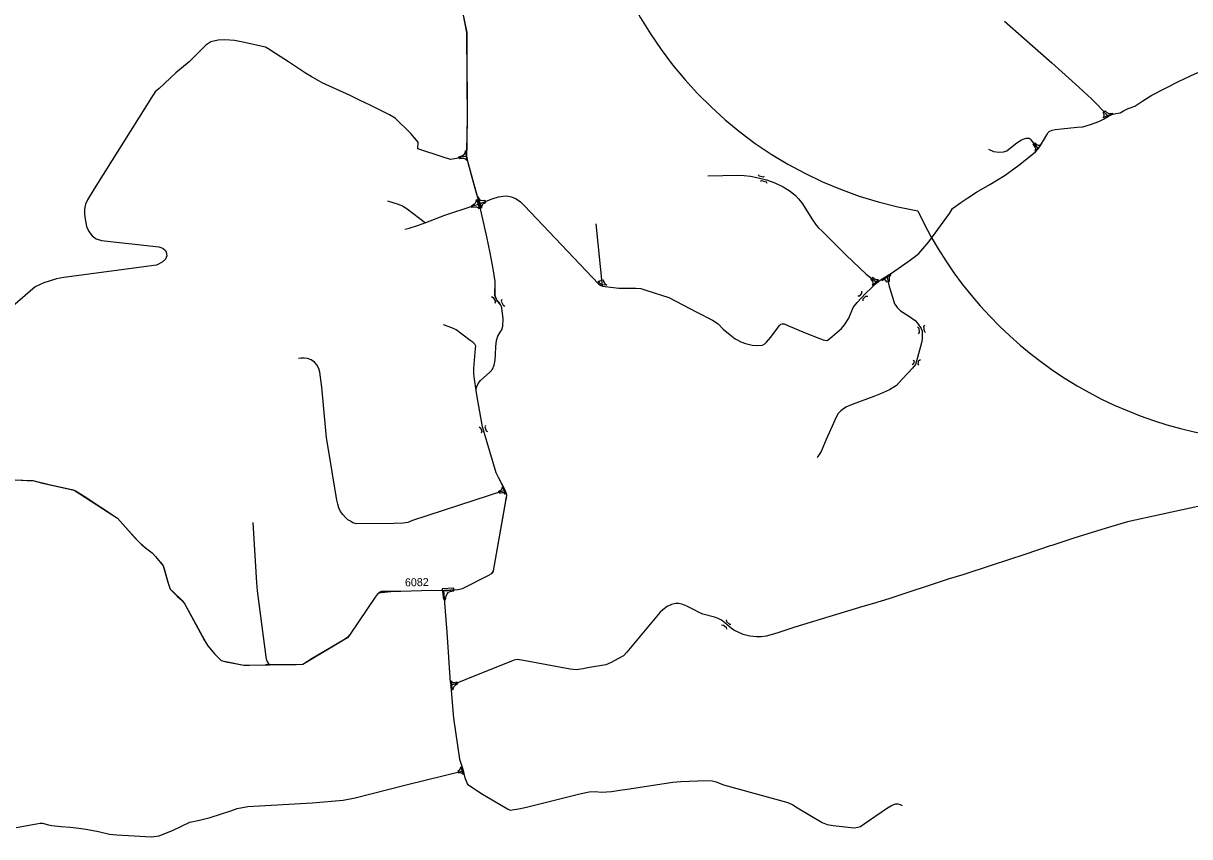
# Model space of a CAD drawing. Extents: x -444937 to -436355, y -1135022 to -1129798.
# Drawn here: x -443209 to -441751, y -1132819 to -1131803 of the extents above; entities that cross this region are included whole.
import ezdxf

# ---------------------------------------------------------------- set-up
doc = ezdxf.new("R2010")
doc.units = 0
for name, color, linetype in [('01_PARC_VNEJSI', 7, 'Continuous'), ('Vrstva 12', 7, 'Continuous'), ('Vrstva 75', 7, 'Continuous'), ('Vrstva 8', 7, 'Continuous'), ('Vrstva 84', 7, 'Continuous')]:
    doc.layers.add(name, color=color, linetype=linetype)

msp = doc.modelspace()

# ---------------------------------------------------------------- linework, layer by layer
at = {"layer": '01_PARC_VNEJSI'}
for centre, start, end in [((-442005.1, -1131544.8), 171.1162, 260.1073), ((-441638.4, -1131824.9), 205.1413, 269.9118)]:
    msp.add_arc(centre, 500, start, end, dxfattribs=at)
at = {"layer": 'Vrstva 12'}
msp.add_line((-442485.1, -1132131.6), (-442492.7, -1132053.5), dxfattribs=at)
for points in [[(-441982.7, -1131800.5), (-441958.2, -1131821.9), (-441923.5, -1131852.4), (-441889.7, -1131882.8), (-441873.4, -1131897.8), (-441866.7, -1131904.6), (-441860.5, -1131911.2), (-441854.3, -1131917.8)], [(-442654.8, -1131969.1), (-442667.5, -1131971.9), (-442674.7, -1131973.3), (-442684, -1131970.4), (-442715.8, -1131960), (-442715.4, -1131951.4), (-442724.6, -1131940.9), (-442743.9, -1131921.6), (-442750.9, -1131917.6), (-442761.2, -1131912.4), (-442774.5, -1131905.7), (-442788.4, -1131899.3), (-442800.1, -1131893.4), (-442835.1, -1131877.3), (-442849.1, -1131869.7), (-442856.2, -1131865.4), (-442877.2, -1131851.4), (-442893.4, -1131840.9), (-442901.8, -1131835.2), (-442906.1, -1131832.8), (-442934.3, -1131826.6), (-442944.6, -1131824.4), (-442956.8, -1131823.9), (-442965.2, -1131824.1), (-442974.3, -1131826.4), (-442980.8, -1131830.2), (-442989.2, -1131839.1), (-443001.4, -1131851.4), (-443018.1, -1131865.1), (-443039.1, -1131884.4), (-443043.7, -1131888.6), (-443045.2, -1131890.8), (-443047.1, -1131893.7), (-443052.5, -1131902.5), (-443120.3, -1132010), (-443128.4, -1132023.4), (-443131.1, -1132029.1), (-443132.4, -1132035.3), (-443132.4, -1132041.5), (-443131.5, -1132047.9), (-443129.5, -1132056.9), (-443126.9, -1132063.3), (-443122.7, -1132068.7), (-443117.5, -1132072.3), (-443110.9, -1132074.3), (-443039.3, -1132082.5), (-443035.6, -1132083.6), (-443033.7, -1132084.6), (-443031.1, -1132086.9), (-443030.1, -1132088.9), (-443029.5, -1132093.4), (-443030, -1132095.5), (-443030.9, -1132097.9), (-443035.2, -1132101.5), (-443042.3, -1132105.1), (-443158.1, -1132120.6), (-443167, -1132122.3), (-443176.2, -1132125.1), (-443183.1, -1132127.4), (-443193.7, -1132132.4), (-443228.1, -1132161.8)], [(-441940.7, -1131959.3), (-441949.2, -1131948.5), (-441951.7, -1131946.9), (-441955.8, -1131946.8), (-441959.9, -1131948.2), (-441962.4, -1131949.3), (-441968.7, -1131954.2), (-441979.9, -1131962.7), (-441984.5, -1131963.9), (-441989.6, -1131964.5), (-441995.8, -1131963.6), (-442002.2, -1131960.7)], [(-442353.3, -1131993.5), (-442315.8, -1131992.9), (-442308, -1131993.2), (-442299.9, -1131994.2), (-442291.9, -1131995.5), (-442280.1, -1131998.6), (-442269.5, -1132002.4), (-442259.2, -1132007.5), (-442250.3, -1132012.8), (-442243.8, -1132018.1), (-442239.9, -1132022.3), (-442235.7, -1132027.5), (-442222.5, -1132048.4), (-442217.9, -1132055.2), (-442214.9, -1132058.7), (-442210.3, -1132062.9), (-442180.5, -1132092.9), (-442155.4, -1132116.3), (-442142.2, -1132127)], [(-442753.6, -1132024.9), (-442741.7, -1132028.4), (-442735, -1132031.2), (-442728.9, -1132034.7), (-442706.2, -1132052.2)], [(-442638.9, -1132029.1), (-442646.9, -1132031.7), (-442682.3, -1132043.2), (-442706.2, -1132052.2), (-442715.3, -1132055.6), (-442728.3, -1132059.7), (-442731.9, -1132060.8)], [(-442129.8, -1132118.4), (-442126.9, -1132131.8), (-442122.2, -1132146.4), (-442120, -1132153.6), (-442118.5, -1132155.6), (-442116.6, -1132158), (-442112.5, -1132162.3), (-442101.3, -1132169.5), (-442094.2, -1132174.3), (-442091.4, -1132177.5), (-442086.6, -1132184.2), (-442085.5, -1132187.1), (-442085.7, -1132197.6), (-442086.2, -1132202.2), (-442091.2, -1132220.4), (-442093.8, -1132229.4), (-442097.6, -1132233.7), (-442103.5, -1132240.2), (-442110.4, -1132247.6), (-442117.7, -1132255.5), (-442126.2, -1132261), (-442137.5, -1132265.9), (-442146.1, -1132269.3), (-442173, -1132279.2), (-442181, -1132282.5), (-442187.1, -1132287.1), (-442190.3, -1132290.7), (-442193, -1132295.3), (-442196.4, -1132302.7), (-442205.4, -1132323.2), (-442211.8, -1132338), (-442215.7, -1132344.2), (-442216.9, -1132345.9)], [(-442607.4, -1132386.9), (-442722.3, -1132424.3), (-442728.1, -1132426.6), (-442733.9, -1132427.6), (-442745.6, -1132427.9), (-442792.9, -1132428.2), (-442796.8, -1132427.3), (-442799.9, -1132425.2), (-442803.2, -1132423.2), (-442805.9, -1132420.6), (-442809.4, -1132416.9), (-442812.3, -1132413), (-442814.3, -1132408.4), (-442815.7, -1132403.9), (-442816.9, -1132398.9), (-442828.7, -1132328), (-442829.7, -1132320.8), (-442830.5, -1132311.9), (-442835.7, -1132257.5), (-442838.1, -1132238.7), (-442839.2, -1132234.4), (-442841.8, -1132229.6), (-442844.8, -1132226.4), (-442849.1, -1132223.6), (-442853.7, -1132221.9), (-442857.8, -1132221.2), (-442861.4, -1132221.2), (-442864.9, -1132221.7)], [(-443218.9, -1132373.2), (-443203.8, -1132374.1), (-443196.6, -1132374.4), (-443184.8, -1132377.4), (-443145.3, -1132386.4), (-443142.5, -1132387.7), (-443132.5, -1132394), (-443091, -1132421.4), (-443068.6, -1132446.5), (-443061.1, -1132454), (-443052.8, -1132460.9), (-443047.7, -1132464.7), (-443041, -1132472), (-443037.3, -1132476.4), (-443034, -1132481), (-443032.7, -1132484.6), (-443027.5, -1132502.6), (-443025, -1132510.1), (-443021, -1132513.9), (-443010, -1132524.3), (-443007, -1132528.8), (-442980.8, -1132576.6), (-442978.1, -1132580.9), (-442969.2, -1132591.3), (-442961.6, -1132599.2), (-442953.4, -1132600.9), (-442933.2, -1132605.1), (-442926.2, -1132605), (-442901.2, -1132604.4)], [(-442682.2, -1132512.2), (-442698, -1132511.8), (-442736.9, -1132512.7), (-442742.3, -1132512.8), (-442749.7, -1132512.8), (-442761.5, -1132513.1), (-442764, -1132514), (-442766.3, -1132516.7), (-442768.9, -1132519.9), (-442800.2, -1132566.2), (-442803.5, -1132570.6), (-442808.5, -1132573.7), (-442857.4, -1132602.8), (-442859.5, -1132604), (-442867.6, -1132604.3), (-442901.2, -1132604.4), (-442903.9, -1132599.9), (-442904.6, -1132597.4), (-442905.1, -1132594.4), (-442915.9, -1132512), (-442916.9, -1132502.1), (-442921.4, -1132426.9)], [(-441925.4, -1132456), (-441957.4, -1132466.6), (-441998.1, -1132480.1), (-442034.7, -1132492), (-442053.2, -1132497.6), (-442127, -1132522), (-442146.2, -1132527.7), (-442159.8, -1132531.5), (-442244.7, -1132557.5), (-442267.1, -1132564.9), (-442280.3, -1132568.7), (-442286.5, -1132569.6), (-442292.5, -1132569.7), (-442301, -1132568.7), (-442309.1, -1132566.6), (-442320.9, -1132561.1), (-442324.2, -1132558.9), (-442332, -1132552.1), (-442336.4, -1132548.7), (-442340.5, -1132546.5), (-442344.9, -1132545), (-442359.6, -1132541.1), (-442364.2, -1132539.1), (-442370.3, -1132535.8), (-442379.4, -1132531.3), (-442386, -1132528.6), (-442389.4, -1132527.9), (-442393.4, -1132527.8), (-442398.6, -1132529.1), (-442404.2, -1132531.7), (-442409.7, -1132535.6), (-442413, -1132538.9), (-442454.6, -1132588.8), (-442458.8, -1132593.3), (-442465.6, -1132597.2), (-442474.3, -1132601.4), (-442480.9, -1132604.3), (-442503.5, -1132608.4), (-442509.1, -1132609.4), (-442518, -1132610.8), (-442525.3, -1132609.9), (-442583.6, -1132599.1), (-442591.4, -1132597.8), (-442595.3, -1132598.5), (-442606.9, -1132603.2), (-442655.8, -1132623), (-442675.2, -1132630.7)], [(-443217.5, -1132807.6), (-443192.3, -1132803.2), (-443187.4, -1132802.3), (-443184.6, -1132802.1), (-443177, -1132804.2), (-443173.1, -1132805.2), (-443161.5, -1132806.4), (-443150.1, -1132807.4), (-443139.3, -1132808.4), (-443135.8, -1132808.8), (-443127.9, -1132810.4), (-443114.7, -1132812.9), (-443100.9, -1132815.9), (-443091.8, -1132816.8), (-443070, -1132818.1), (-443048.9, -1132819.2), (-443038.8, -1132818.3), (-443021.4, -1132811.2), (-443000.4, -1132801.2), (-442988.4, -1132798.7), (-442975, -1132795.4), (-442949.5, -1132786.7), (-442941.6, -1132783.9), (-442928.2, -1132781.4), (-442913.7, -1132780.6), (-442847.6, -1132776.8), (-442809, -1132773.4), (-442794.2, -1132770.5), (-442776.1, -1132766.2), (-442728.8, -1132754), (-442659.1, -1132736.8)]]:
    msp.add_lwpolyline(points, dxfattribs=at)
for points in [[(-441853.1, -1131918.1), (-441859.6, -1131921.3), (-441858.4, -1131920.1), (-441858.1, -1131918.7), (-441858, -1131917.4), (-441858.4, -1131916.2), (-441859.2, -1131914.6), (-441857, -1131912.6), (-441854.8, -1131914.3), (-441853, -1131915.2), (-441850.3, -1131915.8), (-441847.1, -1131915.9), (-441848.9, -1131916.5)], [(-442663.7, -1131972.2), (-442664.3, -1131969.7), (-442659.7, -1131968.1), (-442657.8, -1131967), (-442656.7, -1131965.1), (-442656.2, -1131961.9), (-442655.5, -1131969.5), (-442654.6, -1131974.6), (-442655.8, -1131973.1), (-442657, -1131972.5), (-442658.7, -1131972.1)], [(-441944.5, -1131962.9), (-441943.7, -1131961.5), (-441943.6, -1131959.6), (-441944.5, -1131957.9), (-441946.8, -1131953.6), (-441944.9, -1131952.4), (-441941.8, -1131955), (-441940.5, -1131955.5), (-441939, -1131955.3), (-441937.4, -1131954.5), (-441941.1, -1131959.8)], [(-442648.1, -1132033.1), (-442648.4, -1132030.6), (-442644.7, -1132028.6), (-442643.6, -1132027.3), (-442642.9, -1132025.6), (-442642.3, -1132023.2), (-442640.3, -1132029.5), (-442638.9, -1132035), (-442640.4, -1132033.4), (-442641.8, -1132032.7), (-442643.5, -1132032.6)], [(-442149.6, -1132122.8), (-442147.4, -1132125.5), (-442147, -1132127.2), (-442147.2, -1132128.7), (-442147.8, -1132130.3), (-442144.8, -1132127.5), (-442142.8, -1132125.9), (-442139.9, -1132123.6), (-442141.5, -1132123.7), (-442142.8, -1132123.6), (-442144.2, -1132123.2), (-442147.6, -1132120.6)], [(-442129.5, -1132126.6), (-442130.7, -1132124.5), (-442131.8, -1132123.6), (-442133.2, -1132123.4), (-442135.7, -1132124.2), (-442129.2, -1132119.9), (-442124.7, -1132116.8), (-442126.2, -1132118.8), (-442126.8, -1132120.9), (-442126.9, -1132122.8), (-442126.6, -1132125.8)], [(-442488.7, -1132127.2), (-442488.8, -1132127.1), (-442490.5, -1132125.3), (-442489.2, -1132125.4), (-442488.3, -1132125.2), (-442487.8, -1132124.6), (-442487.3, -1132123.8), (-442484.3, -1132123.5), (-442483.7, -1132125.6), (-442482.5, -1132127.9), (-442481.4, -1132129), (-442479.6, -1132130.4), (-442484.6, -1132129.9), (-442487, -1132128.9)], [(-442613.3, -1132390.3), (-442614.5, -1132387.7), (-442612, -1132386.4), (-442610.6, -1132385.2), (-442610.2, -1132384), (-442610, -1132382.2), (-442607.8, -1132387), (-442606.9, -1132389.5), (-442606.5, -1132391.4), (-442607.6, -1132390.1), (-442608.4, -1132389.6), (-442610, -1132389.5)], [(-442673.7, -1132624.5), (-442673.1, -1132625.8), (-442672.1, -1132626.5), (-442670.7, -1132626.6), (-442666.9, -1132625.9), (-442666, -1132628.1), (-442669, -1132630.5), (-442670.5, -1132632), (-442671.5, -1132633.5), (-442672.5, -1132636.1), (-442673.1, -1132630.4)], [(-442658.8, -1132741.6), (-442660.2, -1132740.4), (-442661, -1132739.9), (-442662.7, -1132739.6), (-442664.6, -1132739.7), (-442665.5, -1132736.8), (-442663.8, -1132736), (-442662.7, -1132735), (-442662.2, -1132734.1), (-442662.1, -1132732.1), (-442660.4, -1132737.3)]]:
    msp.add_lwpolyline(points, close=True, dxfattribs=at)
at = {"layer": 'Vrstva 75'}
for points in [[(-442710.9, -1131594.9), (-442706.9, -1131607), (-442692, -1131690.1), (-442685.9, -1131704.1), (-442679.8, -1131715.5), (-442679.7, -1131716.4), (-442682.3, -1131728.8), (-442683.4, -1131734.7), (-442683.4, -1131741), (-442680.5, -1131748.2), (-442676.8, -1131757.3), (-442659.6, -1131790.8), (-442654.9, -1131814.6), (-442654.2, -1131926), (-442654.7, -1131960.9), (-442654.7, -1131968.9), (-442653.6, -1131975.5), (-442649.2, -1131992.5), (-442644.4, -1132008.9), (-442640.4, -1132023.4)], [(-442615.1, -1132370.5), (-442616.3, -1132368.1), (-442617.8, -1132364.6), (-442629.1, -1132326.7), (-442632.6, -1132314.4), (-442634.7, -1132307.1), (-442641.5, -1132269.6), (-442642.7, -1132261.8), (-442642.7, -1132259.4), (-442642, -1132256.9), (-442640.4, -1132252.9), (-442637.5, -1132249.2), (-442625.8, -1132238.9), (-442622.5, -1132235.2), (-442620.4, -1132230.2), (-442619.2, -1132223.7), (-442618.5, -1132216.8), (-442618.2, -1132206.9), (-442617.2, -1132199.2), (-442615.6, -1132194.1), (-442611.9, -1132187.8), (-442610.8, -1132186.1), (-442609.3, -1132181.6), (-442609, -1132172.1), (-442610.7, -1132158.7), (-442611.8, -1132155.3), (-442617, -1132149), (-442619.1, -1132143.1), (-442619.1, -1132138), (-442619.1, -1132125.6), (-442621.4, -1132109.7), (-442625.5, -1132089.9), (-442629.6, -1132069.9), (-442636, -1132040.2), (-442638.4, -1132031.3), (-442640.4, -1132023.4)], [(-443218.9, -1132373.2), (-443199.5, -1132374.1), (-443196.6, -1132374.4), (-443174.8, -1132379.5), (-443148.1, -1132385.4), (-443145.3, -1132386.4), (-443095.7, -1132418.4), (-443091, -1132421.4), (-443084.3, -1132428.7), (-443065.7, -1132449.6), (-443057.8, -1132457.1), (-443047.7, -1132464.7), (-443043.3, -1132469.2), (-443034, -1132481), (-443032.2, -1132486.5), (-443027.9, -1132501.2), (-443025, -1132510.1), (-443016.4, -1132518.6), (-443010, -1132524.3), (-443007, -1132528.8), (-442982.4, -1132573.9), (-442978.1, -1132580.9), (-442969.2, -1132591.3), (-442961.6, -1132599.2), (-442955.1, -1132600.8), (-442933.2, -1132605.1), (-442906.1, -1132604.4)], [(-442683.8, -1132512), (-442682.9, -1132512), (-442665.8, -1132510.2), (-442659.9, -1132509.2), (-442627.8, -1132493.1), (-442623.2, -1132490.5), (-442621.2, -1132487), (-442605.6, -1132399.6), (-442605.2, -1132396.8), (-442604.6, -1132392.8), (-442604.9, -1132390.7), (-442606.6, -1132386.5), (-442615.1, -1132370.5)], [(-442683.8, -1132512), (-442698, -1132511.8), (-442736.9, -1132512.7), (-442742.3, -1132512.8), (-442749.4, -1132513.5), (-442761.5, -1132514.5), (-442764, -1132514.8), (-442766.3, -1132516.7), (-442768.9, -1132519.9), (-442800.2, -1132566.2), (-442802.6, -1132569), (-442804.5, -1132570.8), (-442809.2, -1132574.1), (-442847.7, -1132596.8), (-442859.5, -1132604), (-442881.4, -1132604.5), (-442906.2, -1132604.4)]]:
    msp.add_lwpolyline(points, dxfattribs=at)
at = {"layer": 'Vrstva 8'}
for points in [[(-442704.8, -1131620.8), (-442701.3, -1131638.8), (-442691.9, -1131690.4), (-442685.9, -1131704.4), (-442679.5, -1131716.1), (-442680.7, -1131721.7), (-442682.3, -1131728.8), (-442683.4, -1131734.7), (-442683.4, -1131741), (-442680.5, -1131748.2), (-442676.2, -1131758.2), (-442667.5, -1131775.2), (-442659.6, -1131790.8), (-442654.5, -1131814.4), (-442654.3, -1131843.5), (-442654.2, -1131908.2), (-442654.6, -1131954.8), (-442654.7, -1131968.9), (-442653.6, -1131975.5), (-442640.4, -1132023.4)], [(-441798.4, -1131893), (-441764.2, -1131875.3), (-441744.7, -1131866.2), (-441728.5, -1131859.7), (-441720.1, -1131855.7), (-441709.4, -1131849.4), (-441691, -1131837.5), (-441679.3, -1131828.8), (-441673.8, -1131822.2), (-441676.8, -1131822), (-441676.8, -1131822)], [(-442639.9, -1132028.9), (-442622.9, -1132022.4), (-442615, -1132019.8), (-442609.1, -1132019), (-442604.3, -1132018.6), (-442598.8, -1132019.9), (-442592.9, -1132022.5), (-442587.4, -1132026), (-442582.2, -1132030.9), (-442490.1, -1132128.4), (-442487.9, -1132130.4), (-442485.1, -1132131.6), (-442481.5, -1132131.9), (-442464.6, -1132133.8), (-442458.8, -1132133.9), (-442443.1, -1132133.8), (-442437, -1132134.5), (-442430.8, -1132136.5), (-442402.2, -1132145.7), (-442366.9, -1132163.8), (-442347.3, -1132173.9), (-442340.6, -1132178.7), (-442334, -1132185.1), (-442325.6, -1132192.2), (-442319.3, -1132197.3), (-442315.8, -1132199), (-442312.2, -1132200.9), (-442306.3, -1132202.9), (-442298.1, -1132205.1), (-442290.8, -1132205.4), (-442284.9, -1132205.1), (-442282.2, -1132203.7), (-442280.2, -1132201.4), (-442274.7, -1132195.2), (-442266.3, -1132184.1), (-442264.2, -1132181.2), (-442262, -1132179.1), (-442260.3, -1132178.5), (-442258.1, -1132178.6), (-442253.3, -1132180.4), (-442231.8, -1132189.7), (-442214.5, -1132196.3), (-442209.4, -1132198.3), (-442207, -1132199.1), (-442204.4, -1132199.2), (-442200.9, -1132196.7), (-442186.3, -1132184.5), (-442182.5, -1132179.8), (-442177.1, -1132171.4), (-442171.8, -1132158.2), (-442166.7, -1132151.9), (-442156.5, -1132140.7), (-442148.5, -1132133.1), (-442146.2, -1132131), (-442142, -1132127.4), (-442139.5, -1132125.3), (-442135.4, -1132122.1), (-442123.9, -1132115.1), (-442102.9, -1132100.6), (-442095.7, -1132095.2), (-442089.7, -1132090.7), (-442077.3, -1132076.1), (-442051.4, -1132040.7), (-442047.5, -1132034.5), (-442037.2, -1132027.1), (-442028.3, -1132021), (-442017.6, -1132014.1), (-442000.8, -1132004.3), (-441981.7, -1131992.6), (-441964.6, -1131980.4), (-441950.6, -1131969), (-441943.7, -1131963.7), (-441940, -1131959.6), (-441933.8, -1131949.5), (-441929.8, -1131942.3), (-441928.2, -1131939.4), (-441926.7, -1131938.2), (-441923.1, -1131936.4), (-441919.3, -1131935.7), (-441911.2, -1131934.8), (-441891.7, -1131933), (-441884.9, -1131932.3), (-441875.3, -1131929.6), (-441864.9, -1131925.9), (-441859, -1131922.8), (-441852.7, -1131918.9), (-441848.4, -1131917.1), (-441843.7, -1131915.8), (-441838.2, -1131914.8), (-441833.8, -1131912.6), (-441828.1, -1131909.7), (-441824.2, -1131908.4), (-441819.9, -1131906.4), (-441809.9, -1131900), (-441798.4, -1131893)], [(-442615.1, -1132370.5), (-442616.3, -1132368.1), (-442617.8, -1132364.6), (-442629.1, -1132326.7), (-442632.6, -1132314.4), (-442634.7, -1132307.1), (-442641.5, -1132269.6), (-442642.7, -1132261.8), (-442642.7, -1132259.4), (-442642, -1132256.9), (-442640.4, -1132252.9), (-442637.5, -1132249.2), (-442625.8, -1132238.9), (-442622.5, -1132235.2), (-442620.4, -1132230.2), (-442619.2, -1132223.7), (-442618.5, -1132216.8), (-442618.2, -1132206.9), (-442617.2, -1132199.2), (-442615.6, -1132194.1), (-442611.9, -1132187.8), (-442610.8, -1132186.1), (-442609.3, -1132181.6), (-442609, -1132172.1), (-442610.7, -1132158.7), (-442611.8, -1132155.3), (-442614.1, -1132152), (-442617.1, -1132148.8), (-442619.3, -1132143.3), (-442619.1, -1132125.6), (-442621.4, -1132109.7), (-442625.5, -1132089.9), (-442629.6, -1132069.9), (-442636, -1132040.2), (-442638.4, -1132031.3), (-442640.4, -1132023.4)], [(-442642.7, -1132261.8), (-442645, -1132247.7), (-442645.6, -1132240.9), (-442645.6, -1132234.2), (-442643.6, -1132209.5), (-442643.3, -1132206.3), (-442644.5, -1132203.8), (-442646.6, -1132201.9), (-442650.1, -1132199.3), (-442667.6, -1132186.2), (-442673, -1132183.3), (-442683.5, -1132179.8)], [(-442674.8, -1132626.4), (-442679.1, -1132563.9), (-442683.3, -1132511.2), (-442665.8, -1132510.2), (-442659.9, -1132509.2), (-442627.8, -1132493.1), (-442623.2, -1132490.5), (-442622, -1132489.2), (-442621.2, -1132487), (-442605.8, -1132400.2), (-442605.1, -1132396.1), (-442604.5, -1132392.6), (-442605.4, -1132389.6), (-442606.5, -1132386.9), (-442615.1, -1132370.5)], [(-441723.8, -1132403), (-441786.7, -1132416.5), (-441829.1, -1132426), (-441860.8, -1132435.3), (-441896, -1132446.1), (-441923.4, -1132455.4), (-441925.4, -1132456)], [(-442674.8, -1132626.4), (-442671.2, -1132671.1), (-442663.8, -1132722.3), (-442659.4, -1132734.8), (-442656.8, -1132745.6), (-442653.8, -1132753.5), (-442647.1, -1132758.1), (-442641.8, -1132761.7), (-442634.8, -1132765.9), (-442613.7, -1132778.6), (-442603.8, -1132784.5), (-442600.4, -1132786.1), (-442587.6, -1132784), (-442578.4, -1132781.9), (-442511.4, -1132765.1), (-442501.4, -1132763.2), (-442494, -1132762.6), (-442486, -1132763.5), (-442473.7, -1132762.7), (-442463.3, -1132760.9), (-442454, -1132759.9), (-442397.2, -1132751), (-442387, -1132750.1), (-442355.2, -1132748.9), (-442347.9, -1132749.3), (-442343.1, -1132750.8), (-442333.7, -1132754.4), (-442253.2, -1132776.6), (-442247, -1132779.4), (-442241.4, -1132783), (-442210.6, -1132801.5), (-442204.4, -1132803.9), (-442196.9, -1132805.2), (-442170.3, -1132808), (-442165.9, -1132807.5), (-442162.5, -1132806.3), (-442158, -1132803.3), (-442130, -1132784), (-442124, -1132780.2), (-442118.8, -1132778.2), (-442115.8, -1132778.1), (-442113.1, -1132778.8), (-442110.6, -1132780.4)]]:
    msp.add_lwpolyline(points, dxfattribs=at)
for points in [[(-442640.4, -1132019.7), (-442639, -1132022.6), (-442637.3, -1132023.9), (-442634.9, -1132024.4), (-442632, -1132024.1), (-442631.2, -1132027.5), (-442633.9, -1132028.5), (-442635.3, -1132029.7), (-442636.1, -1132032.3), (-442636.1, -1132034.2), (-442637.8, -1132027.7)], [(-442685.3, -1132509.5), (-442683.6, -1132522.6), (-442681.1, -1132523.5), (-442680.1, -1132518.9), (-442679.2, -1132515.9), (-442677.4, -1132513.9), (-442675.4, -1132512.9), (-442670.5, -1132512.2), (-442670.7, -1132508.7)]]:
    msp.add_lwpolyline(points, close=True, dxfattribs=at)
at = {"layer": 'Vrstva 84'}
for points in [[(-442290.4, -1131992.2), (-442289, -1131993.7), (-442284.3, -1131995), (-442282.8, -1131993.9)], [(-442287.7, -1132000.4), (-442286.1, -1131999.5), (-442280.6, -1132001), (-442279.6, -1132002.9)], [(-442623.7, -1132144.3), (-442621.4, -1132145.7), (-442618.7, -1132150.8), (-442619.5, -1132153.2)], [(-442610.8, -1132148.1), (-442611.4, -1132150.4), (-442609, -1132155.1), (-442607.1, -1132156.6)], [(-442166, -1132143.7), (-442163.6, -1132143.5), (-442160.7, -1132140.5), (-442161, -1132137.9)], [(-442159.2, -1132149.6), (-442159.2, -1132147.3), (-442156, -1132143.9), (-442153.6, -1132144)], [(-442082.7, -1132180.2), (-442083.7, -1132181.7), (-442083, -1132187.8), (-442081.3, -1132189.5)], [(-442091.5, -1132182.4), (-442089.8, -1132183.8), (-442089.1, -1132189.2), (-442090.4, -1132190.8)], [(-442096.8, -1132223.8), (-442095.4, -1132224.8), (-442096.2, -1132228.5), (-442098.2, -1132229.6)], [(-442089.7, -1132230.1), (-442090.5, -1132228.8), (-442089.5, -1132224.2), (-442087.7, -1132223.1)], [(-442639.2, -1132307.1), (-442637.2, -1132308.4), (-442635.7, -1132313.2), (-442636.7, -1132315.2)], [(-442631.2, -1132305.7), (-442632.1, -1132307.3), (-442630.5, -1132312), (-442628.5, -1132312.9)], [(-442336.2, -1132554.7), (-442333.7, -1132554.8), (-442330.3, -1132557.5), (-442329.8, -1132559.8)], [(-442330.5, -1132548.4), (-442330.1, -1132550.2), (-442326.2, -1132553.5), (-442324.4, -1132553.5)]]:
    msp.add_lwpolyline(points, dxfattribs=at)

# ---------------------------------------------------------------- texts
at = {"layer": 'Vrstva 75'}
msp.add_text('6082', height=10, rotation=1.311, dxfattribs=at).set_placement((-442731.7, -1132506.6))

doc.saveas('drawing.dxf')
